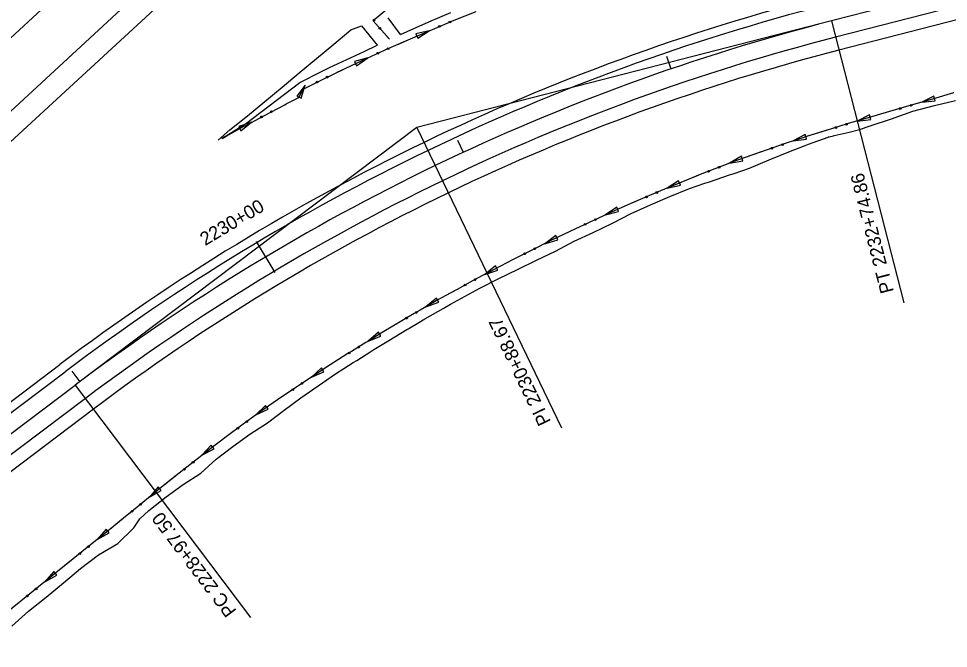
# Model space of a CAD drawing. Extents: x 1611108 to 1749517, y 619561 to 797725.
# Drawn here: x 1727640.7 to 1728056, y 771546.3 to 771827.7 of the extents above; entities that cross this region are included whole.
import ezdxf

# ---------------------------------------------------------------- set-up
doc = ezdxf.new("R2010")
doc.units = 0
for name, color, linetype in [('R_Ditch', 7, 'Continuous'), ('R_Horz Alg', 7, 'Continuous'), ('R_Horz Alg Annot', 7, 'Continuous'), ('R_Horz Alg Stationing', 7, 'Continuous'), ('R_Proposed Const Limits', 7, 'Continuous'), ('R_Proposed Road', 7, 'Continuous')]:
    doc.layers.add(name, color=color, linetype=linetype)

msp = doc.modelspace()

# ---------------------------------------------------------------- linework, layer by layer
at = {"layer": 'R_Ditch'}
for p, q in [((1727824.1, 771822.26), (1727818.17, 771820.87)), ((1727818.17, 771820.87), (1727819, 771818.93)), ((1727819, 771818.93), (1727824.1, 771822.26)), ((1727796.63, 771810.11), (1727790.75, 771808.52)), ((1727790.75, 771808.52), (1727791.65, 771806.61)), ((1727791.65, 771806.61), (1727796.63, 771810.11)), ((1727768.7, 771797.95), (1727765.04, 771793.09)), ((1727766.92, 771792.13), (1727768.7, 771797.95)), ((1727765.04, 771793.09), (1727766.92, 771792.13)), ((1728049.6, 771793.05), (1728044.14, 771790.35)), ((1728044.14, 771790.35), (1728050.19, 771791.02)), ((1728050.19, 771791.02), (1728049.6, 771793.05)), ((1728020.77, 771784.64), (1728015.3, 771781.94)), ((1728015.3, 771781.94), (1728021.36, 771782.61)), ((1728021.36, 771782.61), (1728020.77, 771784.64)), ((1727744.76, 771781.39), (1727738.99, 771779.45)), ((1727738.99, 771779.45), (1727740, 771777.59)), ((1727740, 771777.59), (1727744.76, 771781.39)), ((1727991.99, 771775.89), (1727986.63, 771773.01)), ((1727992.66, 771773.88), (1727991.99, 771775.89)), ((1727986.63, 771773.01), (1727992.66, 771773.88)), ((1727963.54, 771766.18), (1727958.25, 771763.14)), ((1727964.26, 771764.19), (1727963.54, 771766.18)), ((1727958.25, 771763.14), (1727964.26, 771764.19)), ((1727935.51, 771755.25), (1727930.37, 771751.98)), ((1727936.32, 771753.29), (1727935.51, 771755.25)), ((1727930.37, 771751.98), (1727936.32, 771753.29)), ((1727907.88, 771743.4), (1727902.83, 771739.99)), ((1727902.83, 771739.99), (1727908.74, 771741.47)), ((1727908.74, 771741.47), (1727907.88, 771743.4)), ((1727880.6, 771730.73), (1727875.69, 771727.12)), ((1727875.69, 771727.12), (1727881.54, 771728.83)), ((1727881.54, 771728.83), (1727880.6, 771730.73)), ((1727853.75, 771717.18), (1727848.95, 771713.43)), ((1727854.75, 771715.31), (1727853.75, 771717.18)), ((1727848.95, 771713.43), (1727854.75, 771715.31)), ((1727827.34, 771702.81), (1727822.65, 771698.92)), ((1727822.65, 771698.92), (1727828.39, 771700.97)), ((1727828.39, 771700.97), (1727827.34, 771702.81)), ((1727801.39, 771687.64), (1727796.81, 771683.61)), ((1727802.49, 771685.83), (1727801.39, 771687.64)), ((1727796.81, 771683.61), (1727802.49, 771685.83)), ((1727775.92, 771671.66), (1727771.46, 771667.5)), ((1727777.07, 771669.88), (1727775.92, 771671.66)), ((1727771.46, 771667.5), (1727777.07, 771669.88)), ((1727750.95, 771654.9), (1727746.62, 771650.61)), ((1727752.16, 771653.16), (1727750.95, 771654.9)), ((1727746.62, 771650.61), (1727752.16, 771653.16)), ((1727726.7, 771637.09), (1727722.6, 771632.58)), ((1727727.99, 771635.41), (1727726.7, 771637.09)), ((1727722.6, 771632.58), (1727727.99, 771635.41)), ((1727703.09, 771618.48), (1727699.1, 771613.87)), ((1727699.1, 771613.87), (1727704.42, 771616.84)), ((1727704.42, 771616.84), (1727703.09, 771618.48)), ((1727679.76, 771599.55), (1727675.76, 771594.96)), ((1727675.76, 771594.96), (1727681.09, 771597.91)), ((1727681.09, 771597.91), (1727679.76, 771599.55)), ((1727656.4, 771580.68), (1727652.39, 771576.09)), ((1727652.39, 771576.09), (1727657.73, 771579.03)), ((1727657.73, 771579.03), (1727656.4, 771580.68))]:
    msp.add_line(p, q, dxfattribs=at)
for points in [[(1727806.74, 771833.12), (1727799.04, 771826.72), (1727806.35, 771818.5)], [(1727731.62, 771774.15), (1727733.47, 771775.19), (1727740.88, 771779.27), (1727742.43, 771780.12), (1727750.2, 771784.29), (1727759.56, 771789.2), (1727760.28, 771789.57), (1727765.9, 771792.44), (1727767.82, 771796.21), (1727777.31, 771800.92), (1727781.1, 771802.77), (1727786.86, 771805.53), (1727796.45, 771810.03), (1727806.09, 771814.41), (1727815.78, 771818.69), (1727825.51, 771822.87), (1727835.28, 771826.93), (1727845.1, 771830.88)], [(1727810.34, 771816.29), (1727815.78, 771818.69), (1727824.1, 771822.26)], [(1727805.35, 771819.62), (1727805.38, 771819.59)], [(1727805.38, 771819.59), (1727806.35, 771818.5)], [(1727810.3, 771816.28), (1727810.34, 771816.29)], [(1727783.06, 771803.71), (1727786.86, 771805.53), (1727796.45, 771810.03), (1727796.63, 771810.11)], [(1727783.03, 771803.69), (1727783.06, 771803.71)], [(1727758.06, 771788.41), (1727759.56, 771789.2), (1727760.28, 771789.57), (1727765.9, 771792.44), (1727767.82, 771796.21), (1727769.57, 771797.08)], [(1728058.33, 771794.49), (1728049.01, 771791.77), (1728039.4, 771788.97), (1728029.8, 771786.17), (1728020.19, 771783.37), (1728015.38, 771781.97), (1728010.82, 771780.62), (1728004.22, 771778.62), (1728003.87, 771778.51), (1728001.9, 771777.9), (1728001.71, 771777.84), (1728001.48, 771777.77), (1727992.64, 771774.98), (1727991.01, 771774.45), (1727983.6, 771772.01), (1727974.6, 771768.96), (1727965.63, 771765.81), (1727958.8, 771763.34), (1727956.71, 771762.54), (1727947.85, 771759.09), (1727945.83, 771758.29), (1727939.04, 771755.56), (1727930.26, 771751.94), (1727921.53, 771748.24), (1727912.83, 771744.46), (1727904.18, 771740.59), (1727895.57, 771736.64), (1727887, 771732.61), (1727878.47, 771728.5), (1727869.99, 771724.3), (1727861.56, 771720.03), (1727853.17, 771715.67), (1727844.83, 771711.24), (1727836.53, 771706.72), (1727831.56, 771703.97), (1727828.28, 771702.13), (1727820.08, 771697.46), (1727817.41, 771695.91), (1727812.55, 771693.08), (1727811.93, 771692.71), (1727803.83, 771687.89), (1727797.12, 771683.8), (1727795.79, 771682.98), (1727789.38, 771679), (1727787.79, 771678), (1727783.55, 771675.32), (1727779.84, 771672.95), (1727771.95, 771667.82), (1727764.11, 771662.61), (1727756.32, 771657.33), (1727748.59, 771651.98), (1727740.98, 771646.44), (1727733.44, 771640.84), (1727725.95, 771635.17), (1727718.51, 771629.42), (1727711.14, 771623.61), (1727703.83, 771617.72), (1727696.19, 771611.51), (1727691.96, 771608.08), (1727688.42, 771605.2), (1727680.64, 771598.91), (1727672.87, 771592.61), (1727665.08, 771586.32), (1727657.3, 771580.04), (1727649.51, 771573.76), (1727641.71, 771567.49), (1727633.91, 771561.22)], [(1728058.54, 771794.55), (1728058.33, 771794.49), (1728049.01, 771791.77), (1728044.14, 771790.35)], [(1727758.03, 771788.39), (1727758.06, 771788.41)], [(1728029.7, 771786.14), (1728020.19, 771783.37), (1728015.38, 771781.97), (1728015.3, 771781.94)], [(1728029.74, 771786.15), (1728029.7, 771786.14)], [(1727731.62, 771774.15), (1727733.47, 771775.19), (1727740.88, 771779.27), (1727742.43, 771780.12), (1727744.77, 771781.37)], [(1728000.91, 771777.59), (1727992.64, 771774.98), (1727991.01, 771774.45), (1727986.63, 771773.01)], [(1728000.94, 771777.6), (1728000.91, 771777.59)], [(1727972.38, 771768.18), (1727965.63, 771765.81), (1727958.8, 771763.34), (1727958.26, 771763.13)], [(1727972.42, 771768.19), (1727972.38, 771768.18)], [(1727944.25, 771757.66), (1727939.04, 771755.56), (1727930.37, 771751.98)], [(1727944.29, 771757.67), (1727944.25, 771757.66)], [(1727916.54, 771746.07), (1727912.83, 771744.46), (1727904.18, 771740.59), (1727902.84, 771739.98)], [(1727916.58, 771746.09), (1727916.54, 771746.07)], [(1727889.2, 771733.64), (1727887, 771732.61), (1727878.47, 771728.5), (1727875.69, 771727.12)], [(1727889.23, 771733.66), (1727889.2, 771733.64)], [(1727862.25, 771720.38), (1727861.56, 771720.03), (1727853.17, 771715.67), (1727848.95, 771713.43)], [(1727862.28, 771720.39), (1727862.25, 771720.38)], [(1727835.73, 771706.28), (1727831.56, 771703.97), (1727828.28, 771702.13), (1727822.65, 771698.92)], [(1727835.76, 771706.3), (1727835.73, 771706.28)], [(1727809.66, 771691.36), (1727803.83, 771687.89), (1727797.12, 771683.8), (1727796.81, 771683.61)], [(1727809.69, 771691.37), (1727809.66, 771691.36)], [(1727784.06, 771675.64), (1727783.55, 771675.32), (1727779.84, 771672.95), (1727771.95, 771667.82), (1727771.46, 771667.49)], [(1727784.09, 771675.66), (1727784.06, 771675.64)], [(1727758.97, 771659.13), (1727756.32, 771657.33), (1727748.59, 771651.98), (1727746.65, 771650.57)], [(1727759, 771659.15), (1727758.97, 771659.13)], [(1727734.54, 771641.66), (1727733.44, 771640.84), (1727725.95, 771635.17), (1727722.6, 771632.58)], [(1727734.57, 771641.68), (1727734.54, 771641.66)], [(1727710.76, 771623.3), (1727703.83, 771617.72), (1727699.1, 771613.87)], [(1727710.79, 771623.33), (1727710.76, 771623.3)], [(1727687.42, 771604.4), (1727680.64, 771598.91), (1727675.76, 771594.96)], [(1727687.45, 771604.42), (1727687.42, 771604.4)], [(1727664.07, 771585.5), (1727657.3, 771580.04), (1727652.39, 771576.09)], [(1727664.1, 771585.53), (1727664.07, 771585.5)], [(1727640.71, 771566.68), (1727640.68, 771566.66)]]:
    msp.add_lwpolyline(points, dxfattribs=at)
for centre in [(1727799.44, 771827.01), (1727828.7, 771824.23), (1727833.33, 771826.15), (1727802.07, 771823.37), (1727801.17, 771812.22), (1727805.73, 771814.29), (1727774.03, 771799.34), (1727778.53, 771801.56), (1728034.53, 771787.52), (1728039.34, 771788.92), (1727749.16, 771783.77), (1727753.59, 771786.11), (1728005.72, 771779.03), (1728010.51, 771780.49), (1727977.14, 771769.78), (1727981.89, 771771.39), (1727953.6, 771761.29), (1727948.93, 771759.47), (1727925.77, 771750), (1727921.16, 771748.04), (1727898.3, 771737.86), (1727893.76, 771735.75), (1727871.22, 771724.87), (1727866.74, 771722.62), (1727840.15, 771708.65), (1727844.55, 771711.05), (1727818.33, 771696.4), (1727814, 771693.88), (1727788.32, 771678.3), (1727792.58, 771680.94), (1727763.15, 771661.91), (1727767.31, 771664.7), (1727742.63, 771647.59), (1727738.59, 771644.62), (1727718.66, 771629.49), (1727714.73, 771626.39), (1727695.23, 771610.69), (1727691.34, 771607.53), (1727671.89, 771591.78), (1727668, 771588.63), (1727648.52, 771572.92), (1727644.61, 771569.78)]:
    msp.add_circle(centre, 0.375, dxfattribs=at)
at = {"layer": 'R_Horz Alg'}
for p, q in [((1728315.85, 771906.78), (1728003.77, 771826.65)), ((1726803, 771012.63), (1727666.01, 771663.95))]:
    msp.add_line(p, q, dxfattribs=at)
msp.add_arc((1728241.26, 770901.72), 954.93, 104.4, 127.04167, dxfattribs=at)
at = {"layer": 'R_Horz Alg Annot'}
for points in [[(1728003.77, 771826.65), (1727818.61, 771779.11), (1727666.01, 771663.95)], [(1728003.77, 771826.65), (1728036.1, 771700.74)], [(1727818.61, 771779.11), (1727883.25, 771644.92)], [(1727666.01, 771663.95), (1727744.32, 771560.18)]]:
    msp.add_lwpolyline(points, dxfattribs=at)
at = {"layer": 'R_Horz Alg Stationing'}
for points in [[(1727930.13, 771810.89), (1727932.07, 771805.21)], [(1727836.8, 771773.39), (1727839.32, 771767.95)], [(1727746.87, 771728.05), (1727755.09, 771714.32)], [(1727664.41, 771670.25), (1727668.01, 771665.45)]]:
    msp.add_lwpolyline(points, dxfattribs=at)
at = {"layer": 'R_Proposed Const Limits'}
for points in [[(1727811.33, 771820.61), (1727814.25, 771821.97), (1727823.95, 771826.31), (1727833.75, 771830.41)], [(1727789.13, 771822.71), (1727793.92, 771824.43), (1727800.95, 771815.73)], [(1727811.33, 771820.61), (1727805.82, 771828.03)], [(1727729.79, 771773.4), (1727735.07, 771778.06), (1727742.9, 771784.32), (1727750.67, 771790.66), (1727758.38, 771797.05), (1727766.01, 771803.53), (1727773.74, 771809.89), (1727781.47, 771816.26), (1727789.13, 771822.71)], [(1727731.52, 771774.32), (1727733.4, 771775.31), (1727740.57, 771779.82), (1727742.09, 771780.71), (1727766.29, 771799.1), (1727775.74, 771803.96), (1727779.56, 771805.79), (1727785.35, 771808.53), (1727795, 771812.99), (1727800.93, 771815.75)], [(1727637.67, 771556.25), (1727645.14, 771562.95), (1727652.96, 771569.19), (1727660.67, 771575.57), (1727668.38, 771581.95), (1727676.31, 771588.05), (1727685.01, 771593.12), (1727692.18, 771600.22), (1727694.89, 771604.19), (1727698.93, 771607.88), (1727706.66, 771613.96), (1727714.18, 771619.47), (1727722.02, 771624.54), (1727729.01, 771630.8), (1727736.39, 771636.54), (1727743.99, 771641.97), (1727751.82, 771647.06), (1727759.24, 771652.79), (1727766.79, 771658.33), (1727774.54, 771663.58), (1727782.25, 771668.93), (1727785.93, 771671.31), (1727790.12, 771674), (1727791.71, 771675.01), (1727798.06, 771679), (1727799.38, 771679.82), (1727806.04, 771683.91), (1727814.09, 771688.74), (1727814.71, 771689.1), (1727819.53, 771691.94), (1727822.18, 771693.5), (1727830.3, 771698.22), (1727833.55, 771700.07), (1727838.48, 771702.85), (1727846.77, 771707.27), (1727855.15, 771711.51), (1727863.6, 771715.64), (1727872.04, 771719.77), (1727880.56, 771723.73), (1727888.87, 771728.21), (1727897.42, 771732.16), (1727905.93, 771736.23), (1727914.34, 771740.58), (1727922.95, 771744.47), (1727931.6, 771748.28), (1727940.36, 771751.82), (1727947.26, 771754.16), (1727949.31, 771754.83), (1727958.26, 771757.84), (1727960.38, 771758.54), (1727967.23, 771760.8), (1727975.95, 771764.56), (1727984.72, 771768.23), (1727992, 771770.98), (1727993.61, 771771.58), (1728002.31, 771774.76), (1728002.54, 771774.82), (1728002.73, 771774.86), (1728004.73, 771775.34), (1728005.08, 771775.43), (1728011.76, 771777.02), (1728016.38, 771778.1), (1728021.11, 771779.81), (1728030.65, 771782.85), (1728040.1, 771786.27), (1728049.76, 771788.84), (1728059.19, 771791.12)]]:
    msp.add_lwpolyline(points, dxfattribs=at)
at = {"layer": 'R_Proposed Road'}
for p, q in [((1726149.94, 770444.32), (1728095.41, 772242.7)), ((1727151.11, 771337.11), (1728111.7, 772225.07)), ((1727157.9, 771329.77), (1728118.49, 772217.73)), ((1728139.93, 771853.87), (1728005.64, 771819.39)), ((1728141.42, 771848.06), (1728007.13, 771813.58)), ((1727049.16, 771212.82), (1727659.08, 771673.12)), ((1727039.48, 771200.5), (1727661.49, 771669.93)), ((1727670.53, 771657.96), (1726807.51, 771006.65)), ((1727674.14, 771653.17), (1726811.13, 771001.86))]:
    msp.add_line(p, q, dxfattribs=at)
for radius in [966.43, 962.43, 947.43, 941.43]:
    msp.add_arc((1728241.26, 770901.72), radius, 104.4, 127.04167, dxfattribs=at)

# ---------------------------------------------------------------- texts
at = {"layer": 'R_Horz Alg Annot'}
for s, rotation, p in [('PT 2232+74.86', 104.4, (1728031.71, 771705.8)), ('PI 2230+88.67', 115.7208, (1727878.6, 771647.63)), ('PC 2228+97.50', 127.0417, (1727738.31, 771563.16))]:
    msp.add_text(s, height=6, rotation=rotation, dxfattribs=at).set_placement(p)
at = {"layer": 'R_Horz Alg Stationing'}
msp.add_text('2230+00', height=6, rotation=30.8916, dxfattribs=at).set_placement((1727724.02, 771726.03))

doc.saveas('drawing.dxf')
